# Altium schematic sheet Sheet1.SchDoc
size 431 x 279 mm; SheetNumber: 1; SheetTotal: 1; ENG_APP_DATE: --/--/--; DSN_APP_DATE: --/--/--; CHK_APP_DATE: --/--/--
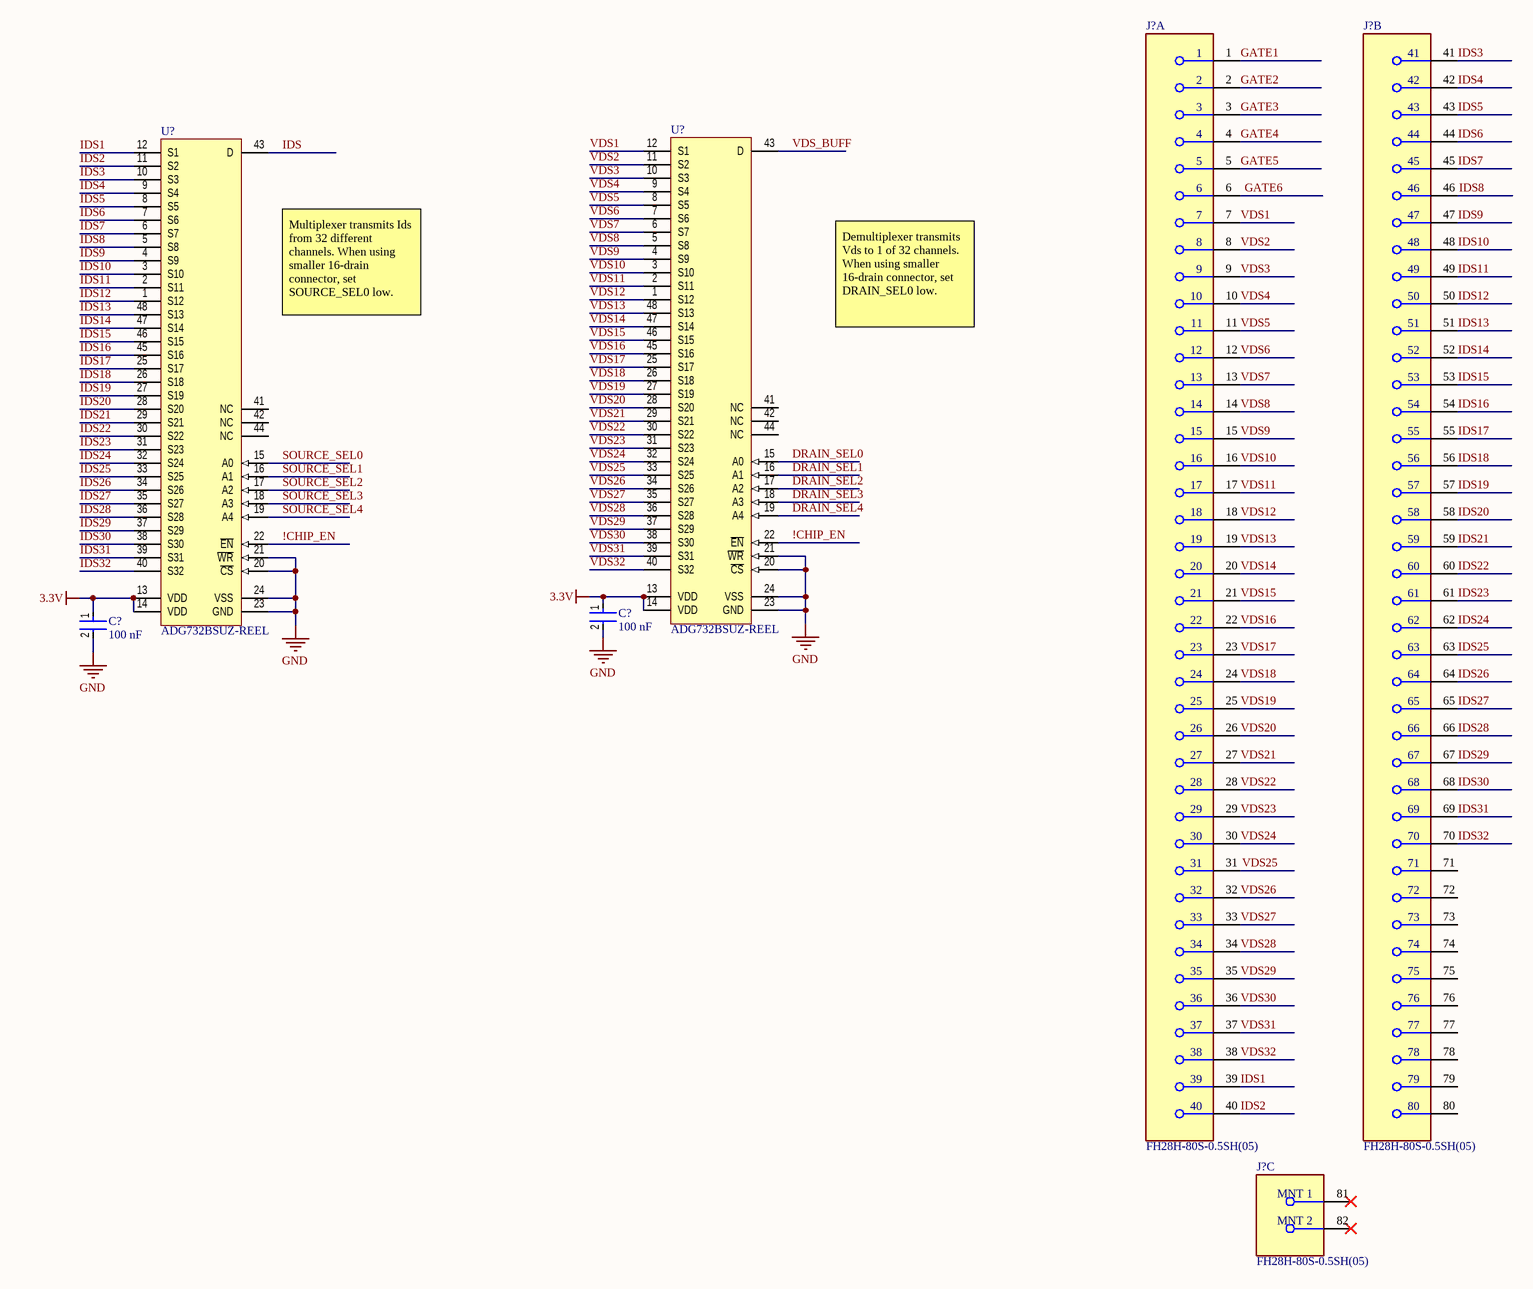
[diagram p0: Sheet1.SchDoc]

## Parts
(Parts that share a designator on the sheet are numbered #1, #2 ... from top to bottom, then left to right.)
C?#1  100 nF  [FP-C0805C-DN-MFG]
C?#2  100 nF  [FP-C0805C-DN-MFG]
J?#1  FH28H-80S-0.5SH(05)  [FP-FH28H-80S-0_5SH_05-MFG]  (part A of 3)
J?#2  FH28H-80S-0.5SH(05)  [FP-FH28H-80S-0_5SH_05-MFG]  (part B of 3)
J?#3  FH28H-80S-0.5SH(05)  [FP-FH28H-80S-0_5SH_05-MFG]  (part C of 3)
U?#1  ADG732BSUZ-REEL  [ADI-SU-48_N]
U?#2  ADG732BSUZ-REEL  [ADI-SU-48_N]

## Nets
3.3V: C?#1.1 C?#2.1 U?#1.13(VDD) U?#1.14(VDD) U?#2.13(VDD) U?#2.14(VDD)
GND: C?#1.2 C?#2.2 U?#1.20(~{CS}) U?#1.21(~{WR}) U?#1.23(GND) U?#1.24(VSS) U?#2.20(~{CS}) U?#2.21(~{WR}) U?#2.23(GND) U?#2.24(VSS)
!CHIP_EN: U?#1.22(~{EN}) U?#2.22(~{EN})
DRAIN_SEL0: U?#2.15(A0)
DRAIN_SEL1: U?#2.16(A1)
DRAIN_SEL2: U?#2.17(A2)
DRAIN_SEL3: U?#2.18(A3)
DRAIN_SEL4: U?#2.19(A4)
GATE1: J?#1.1
GATE2: J?#1.2
GATE3: J?#1.3
GATE4: J?#1.4
GATE5: J?#1.5
GATE6: J?#1.6
IDS: U?#1.43(D)
IDS1: J?#1.39 U?#1.12(S1)
IDS2: J?#1.40 U?#1.11(S2)
IDS3: J?#2.41 U?#1.10(S3)
IDS4: J?#2.42 U?#1.9(S4)
IDS5: J?#2.43 U?#1.8(S5)
IDS6: J?#2.44 U?#1.7(S6)
IDS7: J?#2.45 U?#1.6(S7)
IDS8: J?#2.46 U?#1.5(S8)
IDS9: J?#2.47 U?#1.4(S9)
IDS10: J?#2.48 U?#1.3(S10)
IDS11: J?#2.49 U?#1.2(S11)
IDS12: J?#2.50 U?#1.1(S12)
IDS13: J?#2.51 U?#1.48(S13)
IDS14: J?#2.52 U?#1.47(S14)
IDS15: J?#2.53 U?#1.46(S15)
IDS16: J?#2.54 U?#1.45(S16)
IDS17: J?#2.55 U?#1.25(S17)
IDS18: J?#2.56 U?#1.26(S18)
IDS19: J?#2.57 U?#1.27(S19)
IDS20: J?#2.58 U?#1.28(S20)
IDS21: J?#2.59 U?#1.29(S21)
IDS22: J?#2.60 U?#1.30(S22)
IDS23: J?#2.61 U?#1.31(S23)
IDS24: J?#2.62 U?#1.32(S24)
IDS25: J?#2.63 U?#1.33(S25)
IDS26: J?#2.64 U?#1.34(S26)
IDS27: J?#2.65 U?#1.35(S27)
IDS28: J?#2.66 U?#1.36(S28)
IDS29: J?#2.67 U?#1.37(S29)
IDS30: J?#2.68 U?#1.38(S30)
IDS31: J?#2.69 U?#1.39(S31)
IDS32: J?#2.70 U?#1.40(S32)
SOURCE_SEL0: U?#1.15(A0)
SOURCE_SEL1: U?#1.16(A1)
SOURCE_SEL2: U?#1.17(A2)
SOURCE_SEL3: U?#1.18(A3)
SOURCE_SEL4: U?#1.19(A4)
VDS1: J?#1.7 U?#2.12(S1)
VDS2: J?#1.8 U?#2.11(S2)
VDS3: J?#1.9 U?#2.10(S3)
VDS4: J?#1.10 U?#2.9(S4)
VDS5: J?#1.11 U?#2.8(S5)
VDS6: J?#1.12 U?#2.7(S6)
VDS7: J?#1.13 U?#2.6(S7)
VDS8: J?#1.14 U?#2.5(S8)
VDS9: J?#1.15 U?#2.4(S9)
VDS10: J?#1.16 U?#2.3(S10)
VDS11: J?#1.17 U?#2.2(S11)
VDS12: J?#1.18 U?#2.1(S12)
VDS13: J?#1.19 U?#2.48(S13)
VDS14: J?#1.20 U?#2.47(S14)
VDS15: J?#1.21 U?#2.46(S15)
VDS16: J?#1.22 U?#2.45(S16)
VDS17: J?#1.23 U?#2.25(S17)
VDS18: J?#1.24 U?#2.26(S18)
VDS19: J?#1.25 U?#2.27(S19)
VDS20: J?#1.26 U?#2.28(S20)
VDS21: J?#1.27 U?#2.29(S21)
VDS22: J?#1.28 U?#2.30(S22)
VDS23: J?#1.29 U?#2.31(S23)
VDS24: J?#1.30 U?#2.32(S24)
VDS25: J?#1.31 U?#2.33(S25)
VDS26: J?#1.32 U?#2.34(S26)
VDS27: J?#1.33 U?#2.35(S27)
VDS28: J?#1.34 U?#2.36(S28)
VDS29: J?#1.35 U?#2.37(S29)
VDS30: J?#1.36 U?#2.38(S30)
VDS31: J?#1.37 U?#2.39(S31)
VDS32: J?#1.38 U?#2.40(S32)
VDS_BUFF: U?#2.43(D)

Not connected (* = marked no-connect by the designer): J?#2 71 72 73 74 75 76 77 78 79 80; J?#3 81(MNT_1)* 82(MNT_2)*; U?#1 41(NC) 42(NC) 44(NC); U?#2 41(NC) 42(NC) 44(NC)

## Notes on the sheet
- (near U?#1) Multiplexer transmits Ids from 32 different channels. When using smaller 16-drain connector, set SOURCE_SEL0 low.
- Demultiplexer transmits Vds to 1 of 32 channels. When using smaller 16-drain connector, set DRAIN_SEL0 low.

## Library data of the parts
C?#1 C?#2 = CMP-2007-00279-2: CAP CER 0.1UF 50V X7R 0805; Manufacturer Part Number: C0805C104K5RACTU; Manufacturer: KEMET; Value: 0.10 μF; Tolerance: 0.1; Temperature Coefficient: 30ppm/°C; Material: Ceramic
J?#1-J?#3 = CMP-11609-000031-1: CONN FFC BOTTOM 80POS 0.50MM R/A; Number of Positions: 80; Voltage Rating: 50V; Contact Resistance: 50mR; Max Current Rating: 500mA; Gender: Receptacle; Pitch: 0.5mm; Mating Cycles: 20; Actuator Material: Polymer; Insulation Resistance: 500MR
U?#1 U?#2 = CMP-0798-00236-1: 1.8 to 5.5 V / +/-2.5 V, 4 Ohm, 32-Channel Analog Multiplexer, -40 to 85 degC, 48-pin QFP (SU-48), Reel; Manufacturer: Analog Devices; Ron (ohms): 4; Max Analog Signal Range: Vss to Vdd; Bandwidth (Hz): 18M; Supply V Guar Performance: Dual_(+/-2.5V), Single_(+3V), Single_(+5V); t transition (s): 23n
